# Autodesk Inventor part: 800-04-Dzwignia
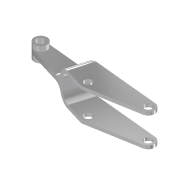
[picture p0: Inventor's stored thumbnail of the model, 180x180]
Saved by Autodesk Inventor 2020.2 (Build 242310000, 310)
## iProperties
Created: 2014-12
Part Number: 800-04-Dzwignia
Material: Aluminium 6061
Document SubType Name: Modeling
Designer: F.Stasiak
Density: 2.7 g/cm^3
Appearance: Aluminium - płaski
Mass: 173.113 g
Surface Area: 276.46 cm^2
Volume: 64.116 cm^3
Catalog Web Link: www.expertbooks.pl
Manager: www.cadconsulting.pl
Company: Fabian Stasiak CAD Consulting
Author: F.Stasiak
Subject: Zbiór ćwiczeń. Autodesk Inventor 2020. Kurs Professional
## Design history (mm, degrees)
sketch "Szkic1"
  geometry: L1 (-105.271, 31.907)-(0, 0); L2 (0, 0)-(78.826, 13.653); L3 (-105.271, 31.907)-(78.826, 13.653); L4 (-104.284, 41.858)-(79.813, 23.604); L5 (80.533, 3.799)-(1.707, -9.853); L6 (-2.901, -9.57)-(-108.171, 22.337); L7 (-36.375, 35.125)-(-45.966, 3.483); L8 (-31.303, 34.622)-(-41.181, 2.033); C1 r 6 at (0, 0); C2 r 6 at (-105.271, 31.907); C3 r 6 at (78.826, 13.653); A1 r 10 centre (0, 0) between (1.707, -9.853) and (-2.901, -9.57); A2 r 10 centre (-105.271, 31.907) between (-104.284, 41.858) and (-108.171, 22.337); A3 r 10 centre (78.826, 13.653) between (79.813, 23.604) and (80.533, 3.799); 1 further point
  constraints: 16 end point, 6 centre point, 6 point on circle, 6 tangent, 5 coincident, 4 point on line, 1 perpendicular
  dimensions: "d0" = 12 diameter of C1; "d1" = 20 diameter of A1; "d2" = 12 diameter of C2; "d3" = 20 diameter of A2; "d4" = 110 distance of L1.start L1.end; "d5" = 12 diameter of C3; "d6" = 20 diameter of A3; "d7" = 80 distance of L1.end L2.end; "d8" = 185 distance of L1.start L2.end; "d19" = 65 distance from line of L1.start L7; "d24" = 5 distance between parallel lines of L8 L7
extrude "Wyciągnięcie proste3" new body sketch "Szkic1" stored distance "d20" = 8; taper "d21" = 0 deg
extrude "Wyciągnięcie proste5" join sketch "Szkic1" stored distance "d25" = 50; taper "d26" = 0 deg
extrude "Wyciągnięcie proste6" cut sketch "Szkic1" stored distance "d27" = 40; taper "d28" = 0 deg
fillet "Zaokrąglenie2" dims "d29" = 12
fillet "Zaokrąglenie3" dims "d30" = 17
extrude "Wyciągnięcie proste7" join sketch "Szkic1" stored distance "d31" = 23; taper "d32" = 0 deg
node "Bryła2"
